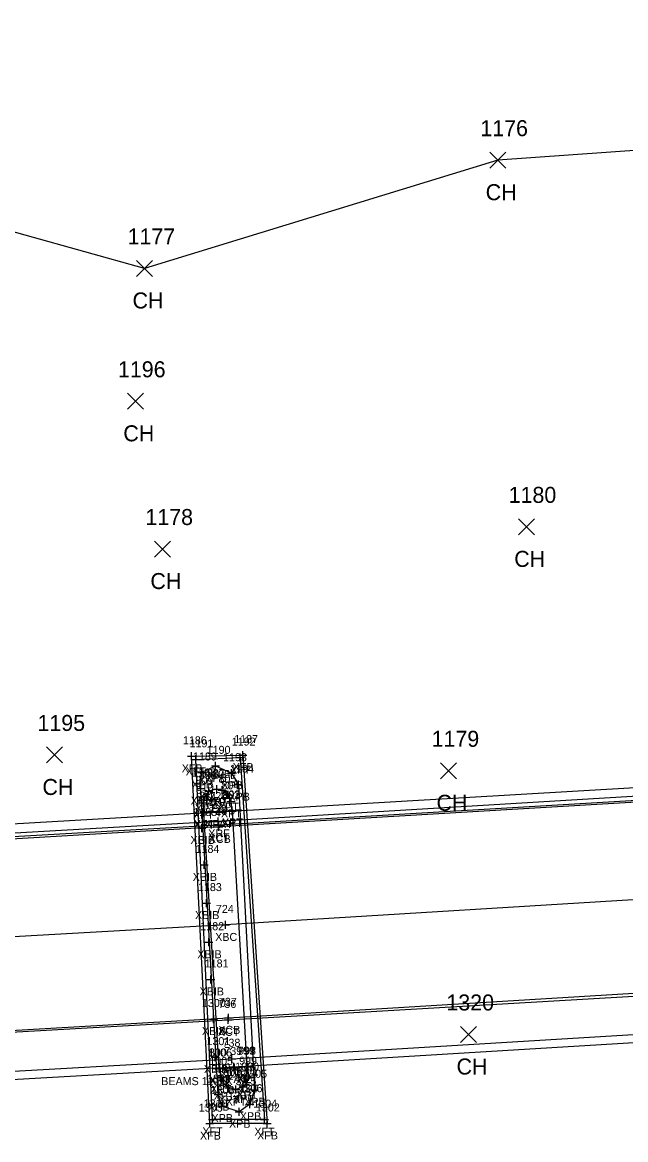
# Model space of a CAD drawing. Extents: x 1716490 to 1717645, y 888034 to 890004.
# Drawn here: x 1716912.5 to 1716987.9, y 888207 to 888346.6 of the extents above; entities that cross this region are included whole.
import ezdxf

# ---------------------------------------------------------------- set-up
doc = ezdxf.new("R2010")
doc.units = 0
for name, color, linetype in [('B_A', 7, 'Continuous'), ('B_C', 7, 'Continuous'), ('B_I', 7, 'Continuous'), ('B_TIC', 7, 'Continuous'), ('BDC', 7, 'Continuous'), ('BELB', 7, 'Continuous'), ('BF', 7, 'Continuous'), ('BFT', 7, 'Continuous'), ('BR', 7, 'Continuous'), ('BSUBM', 7, 'Continuous'), ('L_A', 7, 'Continuous'), ('L_I', 7, 'Continuous'), ('L_TIC', 7, 'Continuous'), ('LSOGP', 7, 'Continuous')]:
    doc.layers.add(name, color=color, linetype=linetype)

msp = doc.modelspace()

# ---------------------------------------------------------------- linework, layer by layer
at = {"layer": 'B_TIC'}
for p, q in [((1716940.04, 888255.07), (1716940.12, 888255.07)), ((1716933.66, 888254.92), (1716933.74, 888254.92)), ((1716934.18, 888254.54), (1716934.25, 888254.54)), ((1716936.65, 888253.73), (1716936.73, 888253.73)), ((1716939.73, 888254.76), (1716939.81, 888254.76)), ((1716934.9, 888252.9), (1716934.97, 888252.9)), ((1716938.65, 888252.81), (1716938.72, 888252.81)), ((1716934.81, 888250.89), (1716934.88, 888250.89)), ((1716939.53, 888251.38), (1716939.6, 888251.38)), ((1716935.36, 888249.9), (1716935.44, 888249.9)), ((1716935.81, 888250.56), (1716935.89, 888250.56)), ((1716936.8, 888250.83), (1716936.88, 888250.83)), ((1716937.48, 888250.71), (1716937.56, 888250.71)), ((1716938.23, 888250.11), (1716938.31, 888250.11)), ((1716935.12, 888249.11), (1716935.2, 888249.11)), ((1716938.6, 888249.29), (1716938.68, 888249.29)), ((1716938.71, 888248.08), (1716938.79, 888248.08)), ((1716938.73, 888248.17), (1716938.81, 888248.17)), ((1716935.18, 888247.85), (1716935.26, 888247.85)), ((1716935.21, 888247.98), (1716935.29, 888247.98)), ((1716936.97, 888246.78), (1716937.05, 888246.78)), ((1716937.11, 888247.95), (1716937.18, 888247.95)), ((1716934.93, 888245.96), (1716935.01, 888245.96)), ((1716937, 888246.31), (1716937.08, 888246.31)), ((1716937.07, 888246.1), (1716937.14, 888246.1)), ((1716935.22, 888241.35), (1716935.3, 888241.35)), ((1716935.52, 888236.58), (1716935.59, 888236.58)), ((1716937.87, 888233.85), (1716937.95, 888233.85)), ((1716935.8, 888231.69), (1716935.88, 888231.69)), ((1716936.08, 888227.04), (1716936.15, 888227.04)), ((1716936.38, 888222.09), (1716936.45, 888222.09)), ((1716938.22, 888221.98), (1716938.3, 888221.98)), ((1716938.26, 888222.24), (1716938.33, 888222.24)), ((1716936.61, 888217.33), (1716936.69, 888217.33)), ((1716938.71, 888217.13), (1716938.78, 888217.13)), ((1716938.93, 888216.1), (1716939.01, 888216.1)), ((1716940.54, 888216.14), (1716940.62, 888216.14)), ((1716940.65, 888216.13), (1716940.73, 888216.13)), ((1716937.08, 888215.92), (1716937.15, 888215.92)), ((1716937.18, 888215.9), (1716937.26, 888215.9)), ((1716937.29, 888214.85), (1716937.37, 888214.85)), ((1716940.78, 888214.88), (1716940.85, 888214.88)), ((1716937.7, 888214), (1716937.77, 888214)), ((1716938.29, 888213.48), (1716938.37, 888213.48)), ((1716939.21, 888213.27), (1716939.28, 888213.27)), ((1716940.11, 888213.62), (1716940.19, 888213.62)), ((1716940.58, 888214.16), (1716940.65, 888214.16)), ((1716941.5, 888213.25), (1716941.58, 888213.25)), ((1716936.98, 888212.65), (1716937.05, 888212.65)), ((1716937.41, 888211.22), (1716937.49, 888211.22)), ((1716939.6, 888210.5), (1716939.67, 888210.5)), ((1716940.95, 888211.45), (1716941.02, 888211.45)), ((1716935.94, 888209.02), (1716936.02, 888209.02)), ((1716936.27, 888209.54), (1716936.35, 888209.54)), ((1716942.76, 888209.52), (1716942.84, 888209.52)), ((1716943.08, 888209.04), (1716943.16, 888209.04))]:
    msp.add_line(p, q, dxfattribs=at)
for points in [[(1716933.66, 888254.42), (1716933.66, 888255.42)], [(1716934.17, 888254.04), (1716934.17, 888255.05)], [(1716939.54, 888255.07), (1716940.54, 888255.07)], [(1716939.73, 888254.26), (1716939.73, 888255.26)], [(1716940.04, 888254.57), (1716940.04, 888255.57)], [(1716933.16, 888254.92), (1716934.16, 888254.92)], [(1716933.67, 888254.54), (1716934.67, 888254.54)], [(1716936.15, 888253.73), (1716937.15, 888253.73)], [(1716936.65, 888253.23), (1716936.65, 888254.23)], [(1716939.23, 888254.76), (1716940.23, 888254.76)], [(1716934.4, 888252.9), (1716935.4, 888252.9)], [(1716934.9, 888252.4), (1716934.9, 888253.4)], [(1716938.15, 888252.81), (1716939.15, 888252.81)], [(1716938.65, 888252.31), (1716938.65, 888253.31)], [(1716934.3, 888250.89), (1716935.3, 888250.89)], [(1716934.8, 888250.39), (1716934.8, 888251.39)], [(1716935.81, 888250.06), (1716935.81, 888251.06)], [(1716936.8, 888250.33), (1716936.8, 888251.33)], [(1716937.48, 888250.21), (1716937.48, 888251.21)], [(1716939.02, 888251.38), (1716940.02, 888251.38)], [(1716939.52, 888250.88), (1716939.52, 888251.88)], [(1716934.86, 888249.9), (1716935.86, 888249.9)], [(1716935.12, 888248.61), (1716935.12, 888249.61)], [(1716935.31, 888250.56), (1716936.31, 888250.56)], [(1716935.36, 888249.4), (1716935.36, 888250.4)], [(1716936.3, 888250.83), (1716937.3, 888250.83)], [(1716936.98, 888250.71), (1716937.98, 888250.71)], [(1716937.73, 888250.11), (1716938.73, 888250.11)], [(1716938.23, 888249.61), (1716938.23, 888250.61)], [(1716938.6, 888248.79), (1716938.6, 888249.79)], [(1716934.62, 888249.11), (1716935.62, 888249.11)], [(1716935.18, 888247.35), (1716935.18, 888248.35)], [(1716935.21, 888247.48), (1716935.21, 888248.48)], [(1716937.1, 888247.45), (1716937.1, 888248.45)], [(1716938.1, 888249.29), (1716939.1, 888249.29)], [(1716938.21, 888248.08), (1716939.21, 888248.08)], [(1716938.23, 888248.17), (1716939.23, 888248.17)], [(1716938.71, 888247.58), (1716938.71, 888248.58)], [(1716938.73, 888247.67), (1716938.73, 888248.67)], [(1716934.68, 888247.85), (1716935.68, 888247.85)], [(1716934.71, 888247.98), (1716935.71, 888247.98)], [(1716936.47, 888246.78), (1716937.47, 888246.78)], [(1716936.6, 888247.95), (1716937.6, 888247.95)], [(1716936.97, 888246.28), (1716936.97, 888247.28)], [(1716937, 888245.81), (1716937, 888246.81)], [(1716934.43, 888245.96), (1716935.43, 888245.96)], [(1716934.93, 888245.46), (1716934.93, 888246.46)], [(1716936.5, 888246.31), (1716937.5, 888246.31)], [(1716936.56, 888246.1), (1716937.56, 888246.1)], [(1716937.06, 888245.6), (1716937.06, 888246.6)], [(1716934.72, 888241.35), (1716935.72, 888241.35)], [(1716935.22, 888240.85), (1716935.22, 888241.85)], [(1716935.51, 888236.08), (1716935.51, 888237.08)], [(1716935.01, 888236.58), (1716936.01, 888236.58)], [(1716937.87, 888233.35), (1716937.87, 888234.35)], [(1716937.37, 888233.85), (1716938.37, 888233.85)], [(1716935.3, 888231.69), (1716936.3, 888231.69)], [(1716935.8, 888231.19), (1716935.8, 888232.19)], [(1716936.07, 888226.54), (1716936.07, 888227.54)], [(1716935.57, 888227.04), (1716936.57, 888227.04)], [(1716935.87, 888222.09), (1716936.87, 888222.09)], [(1716936.37, 888221.59), (1716936.37, 888222.59)], [(1716937.72, 888221.98), (1716938.72, 888221.98)], [(1716937.75, 888222.24), (1716938.75, 888222.24)], [(1716938.22, 888221.48), (1716938.22, 888222.48)], [(1716938.25, 888221.74), (1716938.25, 888222.74)], [(1716936.61, 888216.83), (1716936.61, 888217.83)], [(1716938.7, 888216.63), (1716938.7, 888217.63)], [(1716936.11, 888217.33), (1716937.11, 888217.33)], [(1716937.08, 888215.42), (1716937.08, 888216.42)], [(1716937.18, 888215.4), (1716937.18, 888216.4)], [(1716938.2, 888217.13), (1716939.2, 888217.13)], [(1716938.43, 888216.1), (1716939.43, 888216.1)], [(1716938.93, 888215.6), (1716938.93, 888216.6)], [(1716940.04, 888216.14), (1716941.04, 888216.14)], [(1716940.15, 888216.13), (1716941.15, 888216.13)], [(1716940.54, 888215.64), (1716940.54, 888216.64)], [(1716940.65, 888215.63), (1716940.65, 888216.63)], [(1716936.58, 888215.92), (1716937.58, 888215.92)], [(1716936.68, 888215.9), (1716937.68, 888215.9)], [(1716936.79, 888214.85), (1716937.79, 888214.85)], [(1716937.29, 888214.35), (1716937.29, 888215.35)], [(1716940.27, 888214.88), (1716941.27, 888214.88)], [(1716940.57, 888213.66), (1716940.57, 888214.66)], [(1716940.77, 888214.38), (1716940.77, 888215.38)], [(1716937.19, 888214), (1716938.19, 888214)], [(1716937.69, 888213.5), (1716937.69, 888214.5)], [(1716937.79, 888213.48), (1716938.79, 888213.48)], [(1716938.29, 888212.98), (1716938.29, 888213.98)], [(1716938.7, 888213.27), (1716939.7, 888213.27)], [(1716939.2, 888212.77), (1716939.2, 888213.77)], [(1716939.61, 888213.62), (1716940.61, 888213.62)], [(1716940.07, 888214.16), (1716941.07, 888214.16)], [(1716940.11, 888213.12), (1716940.11, 888214.12)], [(1716941, 888213.25), (1716942, 888213.25)], [(1716941.5, 888212.75), (1716941.5, 888213.75)], [(1716936.47, 888212.65), (1716937.47, 888212.65)], [(1716936.97, 888212.15), (1716936.97, 888213.15)], [(1716940.94, 888210.95), (1716940.94, 888211.95)], [(1716936.91, 888211.22), (1716937.91, 888211.22)], [(1716937.41, 888210.72), (1716937.41, 888211.72)], [(1716939.09, 888210.5), (1716940.09, 888210.5)], [(1716939.59, 888210), (1716939.59, 888211)], [(1716940.44, 888211.45), (1716941.44, 888211.45)], [(1716935.44, 888209.02), (1716936.44, 888209.02)], [(1716935.77, 888209.54), (1716936.77, 888209.54)], [(1716935.94, 888208.52), (1716935.94, 888209.52)], [(1716936.27, 888209.04), (1716936.27, 888210.04)], [(1716942.26, 888209.52), (1716943.26, 888209.52)], [(1716942.58, 888209.04), (1716943.58, 888209.04)], [(1716942.76, 888209.02), (1716942.76, 888210.02)], [(1716943.08, 888208.54), (1716943.08, 888209.54)]]:
    msp.add_lwpolyline(points, dxfattribs=at)
at = {"layer": 'BDC'}
for points in [[(1717176.59, 888262.23), (1717176.88, 888260.81), (1717116.83, 888257.09), (1717056.7, 888253.34), (1716997.03, 888249.86), (1716937, 888246.31), (1716877.5, 888242.93), (1716877.3, 888244.49)], [(1717176.98, 888262.02), (1717176.87, 888260.51), (1717116.83, 888256.95), (1717056.83, 888253.15), (1716997, 888249.66), (1716937.06, 888246.1), (1716877.42, 888242.56)], [(1716878.98, 888212.69), (1716878.75, 888218.61), (1716938.22, 888221.98), (1716998.22, 888225.49), (1717058.32, 888229.07), (1717118.07, 888232.73), (1717177.98, 888236.21), (1717178.1, 888235.65), (1717178.63, 888230.44)], [(1716878.76, 888218.78), (1716938.25, 888222.24), (1716997.85, 888225.86), (1717058.28, 888229.34), (1717118.15, 888232.86), (1717177.91, 888236.5)]]:
    msp.add_lwpolyline(points, dxfattribs=at)
at = {"layer": 'BELB'}
msp.add_lwpolyline([(1717176.82, 888248.24), (1717117.6, 888244.66), (1717057.58, 888241.13), (1716997.66, 888237.53), (1716937.87, 888233.85), (1716878.26, 888230.51)], dxfattribs=at)
at = {"layer": 'BF'}
for points in [[(1717176.59, 888262.23), (1717116.54, 888258.64), (1717056.61, 888254.94), (1716996.92, 888251.43), (1716937.1, 888247.95), (1716877.3, 888244.49)], [(1716878.98, 888212.69), (1716938.93, 888216.1), (1716998.54, 888219.73), (1717058.79, 888223.18), (1717118.39, 888226.86), (1717178.63, 888230.44)]]:
    msp.add_lwpolyline(points, dxfattribs=at)
at = {"layer": 'BFT'}
for points in [[(1716933.66, 888254.92), (1716940.04, 888255.07), (1716943.08, 888209.04), (1716935.94, 888209.02)], [(1716935.94, 888209.02), (1716933.66, 888254.92)], [(1716934.17, 888254.54), (1716939.73, 888254.76), (1716942.76, 888209.52), (1716936.27, 888209.54)], [(1716936.27, 888209.54), (1716934.17, 888254.54)]]:
    msp.add_lwpolyline(points, dxfattribs=at)
at = {"layer": 'BR'}
for points in [[(1717176, 888261.98), (1717175.88, 888261.14), (1717117.06, 888257.61), (1717056.56, 888254), (1716997.02, 888250.41), (1716936.97, 888246.78), (1716878.14, 888243.39), (1716877.96, 888244.41)], [(1716879.62, 888212.9), (1716879.68, 888213.78), (1716938.7, 888217.13), (1716998.52, 888220.76), (1717058.5, 888224.21), (1717118.65, 888227.87), (1717177.58, 888231.53), (1717177.86, 888230.64)]]:
    msp.add_lwpolyline(points, dxfattribs=at)
at = {"layer": 'BSUBM'}
for points in [[(1716934.8, 888250.89), (1716934.9, 888252.9), (1716936.65, 888253.73), (1716938.65, 888252.81), (1716939.52, 888251.38), (1716941.5, 888213.25), (1716940.94, 888211.45), (1716939.59, 888210.5), (1716937.41, 888211.22), (1716936.97, 888212.65)], [(1716936.97, 888212.65), (1716934.8, 888250.89)], [(1716938.73, 888248.17), (1716938.6, 888249.29), (1716938.23, 888250.11), (1716937.48, 888250.71), (1716936.8, 888250.83), (1716935.81, 888250.56), (1716935.36, 888249.9), (1716935.12, 888249.11), (1716935.21, 888247.98)], [(1716940.54, 888216.14), (1716937.08, 888215.92), (1716935.18, 888247.85), (1716938.71, 888248.08)], [(1716935.21, 888247.98), (1716938.73, 888248.17)], [(1716938.71, 888248.08), (1716940.54, 888216.14)], [(1716940.65, 888216.13), (1716940.77, 888214.88), (1716940.57, 888214.16), (1716940.11, 888213.62), (1716939.2, 888213.27), (1716938.29, 888213.48), (1716937.69, 888214), (1716937.29, 888214.85), (1716937.18, 888215.9)], [(1716937.18, 888215.9), (1716940.65, 888216.13)]]:
    msp.add_lwpolyline(points, dxfattribs=at)
at = {"layer": 'L_TIC'}
for points in [[(1716970.92, 888328.41), (1716972.92, 888330.41)], [(1716972.92, 888328.41), (1716970.92, 888330.41)], [(1716926.78, 888314.88), (1716928.78, 888316.88)], [(1716928.78, 888314.88), (1716926.78, 888316.88)], [(1716925.63, 888298.28), (1716927.63, 888300.28)], [(1716927.63, 888298.28), (1716925.63, 888300.28)], [(1716974.49, 888282.59), (1716976.49, 888284.59)], [(1716976.49, 888282.59), (1716974.49, 888284.59)], [(1716929.01, 888279.82), (1716931.01, 888281.82)], [(1716931.01, 888279.82), (1716929.01, 888281.82)], [(1716915.52, 888254.09), (1716917.52, 888256.09)], [(1716917.52, 888254.09), (1716915.52, 888256.09)], [(1716964.78, 888252.11), (1716966.78, 888254.11)], [(1716966.78, 888252.11), (1716964.78, 888254.11)], [(1716967.28, 888219.16), (1716969.28, 888221.16)], [(1716969.28, 888219.16), (1716967.28, 888221.16)]]:
    msp.add_lwpolyline(points, dxfattribs=at)
at = {"layer": 'LSOGP'}
msp.add_lwpolyline([(1717115.57, 888330.22), (1717057.48, 888334.02), (1717034.29, 888346.63), (1716994.9, 888331.05), (1716971.92, 888329.41), (1716927.78, 888315.88), (1716905.33, 888322.14)], dxfattribs=at)

# ---------------------------------------------------------------- texts
at = {"layer": 'B_A'}
for s, p in [('XFB', (1716932.42, 888252.92)), ('XFT', (1716938.47, 888252.76)), ('XFB', (1716938.8, 888253.07)), ('XFT', (1716932.92, 888252.54)), ('XPB', (1716935.38, 888251.73)), ('XPB', (1716933.63, 888250.9)), ('XPB', (1716937.38, 888250.81)), ('XPB', (1716933.54, 888248.89)), ('XPT', (1716934.53, 888248.56)), ('XPT', (1716935.52, 888248.83)), ('XPT', (1716936.2, 888248.71)), ('XPB', (1716938.26, 888249.38)), ('XPT', (1716933.84, 888247.11)), ('XPT', (1716934.08, 888247.9)), ('XPT', (1716936.95, 888248.11)), ('XPT', (1716937.32, 888247.29)), ('XPT', (1716933.9, 888245.85)), ('XPT', (1716933.93, 888245.98)), ('XFAT', (1716935.36, 888245.95)), ('XPT', (1716937.43, 888246.08)), ('XPT', (1716937.45, 888246.17)), ('XCT', (1716935.72, 888244.31)), ('XRF', (1716935.73, 888244.78)), ('XBIB', (1716933.5, 888243.96)), ('XCB', (1716935.8, 888244.1)), ('XBIB', (1716933.79, 888239.35)), ('XBIB', (1716934.08, 888234.58)), ('XBC', (1716936.6, 888231.85)), ('XBIB', (1716934.37, 888229.69)), ('XBIB', (1716934.65, 888225.04)), ('XBIB', (1716934.94, 888220.09)), ('XCT', (1716936.94, 888219.98)), ('XCB', (1716936.99, 888220.24)), ('XBIB', (1716935.18, 888215.33)), ('XRF', (1716937.46, 888215.13)), ('XPT', (1716935.8, 888213.92)), ('XPT', (1716935.9, 888213.9)), ('XFAT', (1716937.18, 888214.1)), ('XPT', (1716939.26, 888214.14)), ('XPT', (1716939.37, 888214.13)), ('XPT', (1716936.01, 888212.85)), ('XPT', (1716939.29, 888212.16)), ('XPT', (1716939.49, 888212.88)), ('XPT', (1716936.41, 888212)), ('XPT', (1716937.01, 888211.48)), ('XPT', (1716937.92, 888211.27)), ('XPT', (1716938.83, 888211.62)), ('XPB', (1716940.23, 888211.25)), ('XPB', (1716935.71, 888210.65)), ('XPB', (1716939.68, 888209.45)), ('XPB', (1716936.14, 888209.22)), ('XPB', (1716938.33, 888208.5)), ('XFB', (1716934.7, 888207.02)), ('XFT', (1716935.01, 888207.54)), ('XFT', (1716941.5, 888207.52)), ('XFB', (1716941.84, 888207.04))]:
    msp.add_text(s, height=1, dxfattribs=at).set_placement(p)
at = {"layer": 'B_C'}
msp.add_text('BEAMS 11.5 X 33.5', height=1, dxfattribs=at).set_placement((1716929.86, 888213.83))
at = {"layer": 'B_I'}
for s, p in [('1186', (1716932.57, 888256.42)), ('1191', (1716933.4, 888256.04)), ('1192', (1716938.67, 888256.26)), ('1187', (1716938.98, 888256.57)), ('1189', (1716933.83, 888254.4)), ('1190', (1716935.54, 888255.23)), ('1193', (1716937.58, 888254.31)), ('1194', (1716938.46, 888252.88)), ('1188', (1716933.74, 888252.39)), ('809', (1716934.13, 888251.4)), ('808', (1716934.59, 888252.06)), ('807', (1716935.58, 888252.33)), ('806', (1716936.23, 888252.21)), ('805', (1716937.01, 888251.61)), ('810', (1716934.18, 888250.61)), ('804', (1716937.38, 888250.79)), ('801', (1716934.24, 888249.35)), ('811', (1716934.6, 888249.48)), ('720', (1716935.88, 888249.45)), ('802', (1716937.49, 888249.58)), ('803', (1716937.51, 888249.67)), ('1185', (1716933.87, 888247.46)), ('722', (1716935.82, 888247.81)), ('723', (1716935.88, 888247.6)), ('721', (1716936.07, 888248.28)), ('1184', (1716934.15, 888242.85)), ('1183', (1716934.45, 888238.08)), ('724', (1716936.69, 888235.35)), ('1182', (1716934.74, 888233.19)), ('1181', (1716935.29, 888228.54)), ('1300', (1716934.94, 888223.59)), ('736', (1716937.01, 888223.48)), ('737', (1716937.07, 888223.74)), ('1301', (1716935.51, 888218.83)), ('738', (1716937.52, 888218.63)), ('1006', (1716935.73, 888217.4)), ('800', (1716935.81, 888217.42)), ('1005', (1716935.86, 888216.35)), ('739', (1716937.74, 888217.6)), ('799', (1716939.35, 888217.64)), ('998', (1716939.47, 888217.63)), ('999', (1716939.59, 888216.38)), ('1004', (1716936.27, 888215.5)), ('1003', (1716936.87, 888214.98)), ('1001', (1716938.97, 888215.12)), ('1000', (1716939.1, 888215.66)), ('1309', (1716935.58, 888214.15)), ('1002', (1716937.78, 888214.77)), ('1305', (1716940.11, 888214.75)), ('1308', (1716936.02, 888212.72)), ('1306', (1716939.53, 888212.95)), ('1310', (1716935.16, 888211.04)), ('1307', (1716938.21, 888212)), ('1304', (1716941.37, 888211.02)), ('1303', (1716934.55, 888210.52)), ('1302', (1716941.69, 888210.54))]:
    msp.add_text(s, height=1, dxfattribs=at).set_placement(p)
at = {"layer": 'L_A'}
for p in [(1716970.41, 888324.41), (1716926.27, 888310.88), (1716925.12, 888294.28), (1716973.98, 888278.59), (1716928.5, 888275.82), (1716915.01, 888250.09), (1716964.27, 888248.11), (1716966.77, 888215.16)]:
    msp.add_text('CH', height=2, dxfattribs=at).set_placement(p)
at = {"layer": 'L_I'}
for s, p in [('1176', (1716969.74, 888332.41)), ('1177', (1716925.65, 888318.88)), ('1196', (1716924.45, 888302.28)), ('1180', (1716973.28, 888286.59)), ('1178', (1716927.88, 888283.82)), ('1195', (1716914.39, 888258.09)), ('1179', (1716963.65, 888256.11)), ('1320', (1716965.5, 888223.16))]:
    msp.add_text(s, height=2, dxfattribs=at).set_placement(p)

doc.saveas('drawing.dxf')
